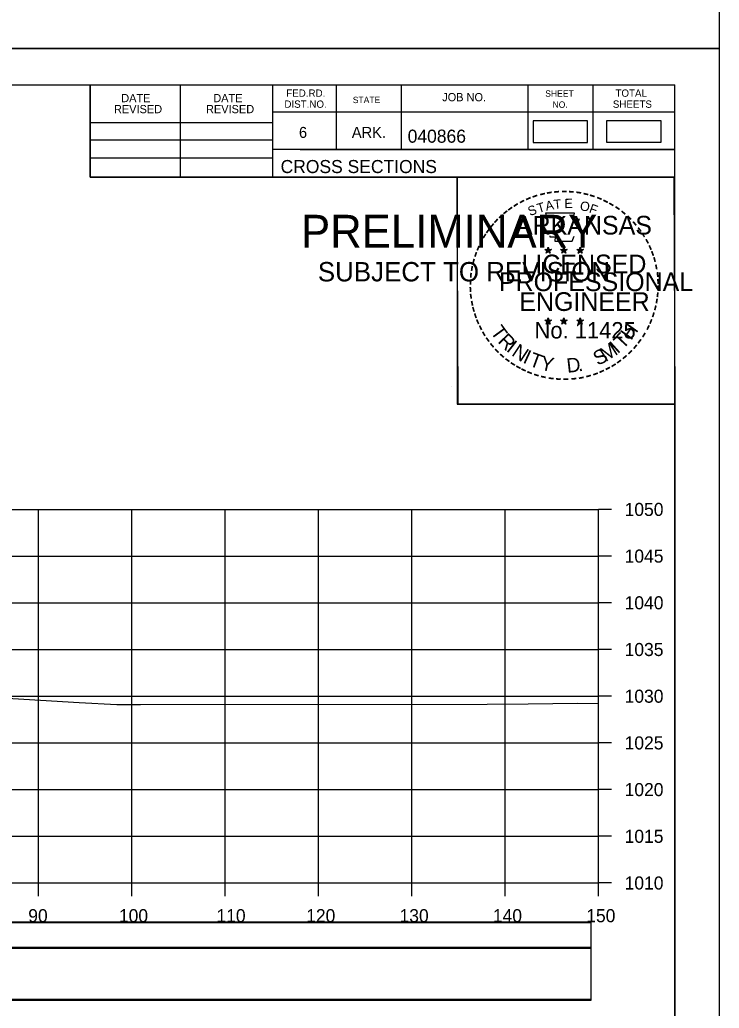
# Model space of a CAD drawing. Extents: x 1370565 to 1374448, y 301010 to 304637.
# Drawn here: x 1373456.8 to 1373531.7, y 302262.2 to 302368.1 of the extents above; entities that cross this region are included whole.
import ezdxf

# ---------------------------------------------------------------- set-up
doc = ezdxf.new("R2010")
doc.units = 0
for name, color, linetype in [('Default', 7, 'Continuous'), ('R_Axis', 7, 'Continuous'), ('R_Axis Annot', 7, 'Continuous'), ('R_Border', 7, 'Continuous'), ('R_Border PE', 7, 'Continuous'), ('R_Border Prem', 7, 'Continuous'), ('R_Drive', 7, 'Continuous'), ('R_Exist Surface', 7, 'Continuous'), ('R_Grid', 7, 'Continuous'), ('R_No Plot', 7, 'Continuous')]:
    doc.layers.add(name, color=color, linetype=linetype)

msp = doc.modelspace()

# ---------------------------------------------------------------- linework, layer by layer
at = {"layer": 'Default'}
for points in [[(1373511.81, 302354.95), (1373517.64, 302354.95), (1373517.64, 302357.26), (1373511.81, 302357.26)], [(1373219.61, 302268.69), (1373518.02, 302268.69), (1373518.02, 302271.39), (1373219.61, 302271.39)], [(1373219.61, 302263.11), (1373518.02, 302263.11), (1373518.02, 302268.63), (1373219.61, 302268.63)]]:
    msp.add_lwpolyline(points, close=True, dxfattribs=at)
at = {"layer": 'R_Axis'}
for p, q in [((1373518.81, 302275.65), (1373518.81, 302315.65)), ((1373520.21, 302315.65), (1373518.81, 302315.65)), ((1373520.21, 302310.65), (1373518.81, 302310.65)), ((1373520.21, 302305.65), (1373518.81, 302305.65)), ((1373520.21, 302300.65), (1373518.81, 302300.65)), ((1373520.21, 302295.65), (1373518.81, 302295.65)), ((1373520.21, 302290.65), (1373518.81, 302290.65)), ((1373520.21, 302285.65), (1373518.81, 302285.65)), ((1373520.21, 302280.65), (1373518.81, 302280.65)), ((1373218.81, 302275.65), (1373518.81, 302275.65)), ((1373458.81, 302274.25), (1373458.81, 302275.65)), ((1373468.81, 302274.25), (1373468.81, 302275.65)), ((1373478.81, 302274.25), (1373478.81, 302275.65)), ((1373488.81, 302274.25), (1373488.81, 302275.65)), ((1373498.81, 302274.25), (1373498.81, 302275.65)), ((1373508.81, 302274.25), (1373508.81, 302275.65)), ((1373518.81, 302274.25), (1373518.81, 302275.65)), ((1373520.21, 302275.65), (1373518.81, 302275.65))]:
    msp.add_line(p, q, dxfattribs=at)
at = {"layer": 'R_Border'}
for p, q in [((1373210.81, 302361.11), (1373526.99, 302361.11)), ((1373464.35, 302351.23), (1373464.35, 302361.11)), ((1373474.03, 302351.23), (1373474.03, 302361.11)), ((1373483.89, 302361.11), (1373483.89, 302351.23)), ((1373490.73, 302361.11), (1373490.73, 302354.17)), ((1373497.67, 302361.11), (1373497.67, 302354.17)), ((1373511.25, 302361.11), (1373511.25, 302354.17)), ((1373518.19, 302361.11), (1373518.19, 302354.17)), ((1373526.99, 302155.65), (1373526.99, 302361.11)), ((1373526.99, 302358.17), (1373483.89, 302358.17)), ((1373526.99, 302358.19), (1373526.99, 302358.19)), ((1373464.35, 302357.09), (1373483.89, 302357.09)), ((1373464.35, 302355.23), (1373483.89, 302355.23)), ((1373526.99, 302354.17), (1373483.89, 302354.17)), ((1373486.85, 302354.17), (1373526.99, 302354.17)), ((1373464.35, 302353.29), (1373483.89, 302353.29)), ((1373526.99, 302351.23), (1373464.35, 302351.23))]:
    msp.add_line(p, q, dxfattribs=at)
at = {"layer": 'R_Border PE'}
for p, q in [((1373513.08, 302343.49), (1373513.43, 302343.37)), ((1373513.08, 302343.49), (1373513.33, 302343.44)), ((1373513.08, 302343.49), (1373513.32, 302343.36)), ((1373513.21, 302343.08), (1373513.43, 302343.37)), ((1373513.21, 302343.08), (1373513.34, 302343.32)), ((1373513.21, 302343.08), (1373513.43, 302343.29)), ((1373513.43, 302343.74), (1373513.39, 302343.49)), ((1373513.43, 302343.37), (1373513.43, 302343.74)), ((1373513.43, 302343.74), (1373513.48, 302343.49)), ((1373513.78, 302343.49), (1373513.43, 302343.37)), ((1373513.64, 302343.08), (1373513.43, 302343.37)), ((1373513.64, 302343.08), (1373513.43, 302343.29)), ((1373513.78, 302343.49), (1373513.49, 302343.44)), ((1373513.64, 302343.08), (1373513.5, 302343.37)), ((1373513.78, 302343.49), (1373513.57, 302343.38)), ((1373514.75, 302343.49), (1373515.1, 302343.37)), ((1373514.75, 302343.49), (1373515, 302343.44)), ((1373514.75, 302343.49), (1373514.99, 302343.36)), ((1373514.88, 302343.08), (1373515.1, 302343.37)), ((1373514.88, 302343.08), (1373515.01, 302343.32)), ((1373514.88, 302343.08), (1373515.1, 302343.29)), ((1373515.1, 302343.74), (1373515.06, 302343.49)), ((1373515.1, 302343.37), (1373515.1, 302343.74)), ((1373515.1, 302343.74), (1373515.15, 302343.49)), ((1373515.45, 302343.49), (1373515.1, 302343.37)), ((1373515.31, 302343.08), (1373515.1, 302343.37)), ((1373515.31, 302343.08), (1373515.1, 302343.29)), ((1373515.45, 302343.49), (1373515.16, 302343.44)), ((1373515.31, 302343.08), (1373515.17, 302343.37)), ((1373515.45, 302343.49), (1373515.24, 302343.38)), ((1373516.51, 302343.47), (1373516.86, 302343.36)), ((1373516.51, 302343.47), (1373516.77, 302343.43)), ((1373516.51, 302343.47), (1373516.75, 302343.35)), ((1373516.65, 302343.07), (1373516.86, 302343.36)), ((1373516.65, 302343.07), (1373516.77, 302343.31)), ((1373516.65, 302343.07), (1373516.86, 302343.28)), ((1373516.86, 302343.73), (1373516.82, 302343.48)), ((1373516.86, 302343.36), (1373516.86, 302343.73)), ((1373516.86, 302343.73), (1373516.91, 302343.48)), ((1373517.21, 302343.47), (1373516.86, 302343.36)), ((1373517.08, 302343.07), (1373516.86, 302343.36)), ((1373517.08, 302343.07), (1373516.86, 302343.28)), ((1373517.21, 302343.47), (1373516.92, 302343.42)), ((1373517.08, 302343.07), (1373516.94, 302343.36)), ((1373517.21, 302343.47), (1373517.01, 302343.37)), ((1373513.08, 302335.91), (1373513.42, 302335.8)), ((1373513.08, 302335.91), (1373513.33, 302335.87)), ((1373513.08, 302335.91), (1373513.31, 302335.79)), ((1373513.21, 302335.5), (1373513.42, 302335.8)), ((1373513.21, 302335.5), (1373513.33, 302335.75)), ((1373513.21, 302335.5), (1373513.42, 302335.72)), ((1373513.42, 302336.17), (1373513.38, 302335.91)), ((1373513.42, 302335.8), (1373513.42, 302336.17)), ((1373513.42, 302336.17), (1373513.47, 302335.92)), ((1373513.77, 302335.91), (1373513.42, 302335.8)), ((1373513.64, 302335.5), (1373513.42, 302335.8)), ((1373513.64, 302335.5), (1373513.42, 302335.72)), ((1373513.77, 302335.91), (1373513.49, 302335.86)), ((1373513.64, 302335.5), (1373513.5, 302335.8)), ((1373513.77, 302335.91), (1373513.57, 302335.81)), ((1373514.74, 302335.91), (1373515.09, 302335.8)), ((1373514.74, 302335.91), (1373515, 302335.87)), ((1373514.74, 302335.91), (1373514.98, 302335.79)), ((1373514.88, 302335.5), (1373515.09, 302335.8)), ((1373514.88, 302335.5), (1373515, 302335.75)), ((1373514.88, 302335.5), (1373515.09, 302335.72)), ((1373515.09, 302336.17), (1373515.05, 302335.91)), ((1373515.09, 302335.8), (1373515.09, 302336.17)), ((1373515.09, 302336.17), (1373515.14, 302335.92)), ((1373515.44, 302335.91), (1373515.09, 302335.8)), ((1373515.31, 302335.5), (1373515.09, 302335.8)), ((1373515.31, 302335.5), (1373515.09, 302335.72)), ((1373515.44, 302335.91), (1373515.15, 302335.86)), ((1373515.31, 302335.5), (1373515.17, 302335.8)), ((1373515.44, 302335.91), (1373515.24, 302335.81)), ((1373516.51, 302335.9), (1373516.86, 302335.79)), ((1373516.51, 302335.9), (1373516.76, 302335.86)), ((1373516.51, 302335.9), (1373516.75, 302335.78)), ((1373516.64, 302335.49), (1373516.86, 302335.79)), ((1373516.64, 302335.49), (1373516.77, 302335.74)), ((1373516.64, 302335.49), (1373516.86, 302335.71)), ((1373516.86, 302336.16), (1373516.82, 302335.9)), ((1373516.86, 302335.79), (1373516.86, 302336.16)), ((1373516.86, 302336.16), (1373516.91, 302335.91)), ((1373517.21, 302335.9), (1373516.86, 302335.79)), ((1373517.07, 302335.49), (1373516.86, 302335.79)), ((1373517.21, 302335.9), (1373516.92, 302335.85)), ((1373517.07, 302335.49), (1373516.94, 302335.79)), ((1373517.21, 302335.9), (1373517, 302335.8)), ((1373517.07, 302335.49), (1373516.86, 302335.71))]:
    msp.add_line(p, q, dxfattribs=at)
for points in [[(1373513.12, 302347.36), (1373513.39, 302346.54)], [(1373516.63, 302346.44), (1373516.77, 302346.73), (1373516.09, 302346.7), (1373516.24, 302347.36), (1373513.12, 302347.36)], [(1373513.61, 302344.94), (1373513.61, 302344.85), (1373514.18, 302344.83), (1373514.12, 302344.36), (1373515.99, 302344.36), (1373516.19, 302344.9)], [(1373513.43, 302343.74), (1373513.64, 302343.08), (1373513.08, 302343.49), (1373513.78, 302343.49), (1373513.21, 302343.08), (1373513.43, 302343.74)], [(1373515.1, 302343.74), (1373515.31, 302343.08), (1373514.75, 302343.49), (1373515.45, 302343.49), (1373514.88, 302343.08), (1373515.1, 302343.74)], [(1373516.86, 302343.73), (1373517.08, 302343.07), (1373516.51, 302343.47), (1373517.21, 302343.47), (1373516.65, 302343.07), (1373516.86, 302343.73)], [(1373513.42, 302336.17), (1373513.64, 302335.5), (1373513.08, 302335.91), (1373513.77, 302335.91), (1373513.21, 302335.5), (1373513.42, 302336.17)], [(1373515.09, 302336.17), (1373515.31, 302335.5), (1373514.74, 302335.91), (1373515.44, 302335.91), (1373514.88, 302335.5), (1373515.09, 302336.17)], [(1373516.86, 302336.16), (1373517.07, 302335.49), (1373516.51, 302335.9), (1373517.21, 302335.9), (1373516.64, 302335.49), (1373516.86, 302336.16)]]:
    msp.add_lwpolyline(points, dxfattribs=at)
for centre, radius in [((1373513.43, 302343.37), 0.172), ((1373513.43, 302343.37), 0.145), ((1373513.43, 302343.37), 0.116), ((1373513.43, 302343.37), 0.0991), ((1373513.43, 302343.37), 0.0747), ((1373513.43, 302343.37), 0.0495), ((1373513.43, 302343.37), 0.0296), ((1373515.1, 302343.37), 0.172), ((1373515.1, 302343.37), 0.145), ((1373515.1, 302343.37), 0.116), ((1373515.1, 302343.37), 0.0991), ((1373515.1, 302343.37), 0.0747), ((1373515.1, 302343.37), 0.0495), ((1373515.1, 302343.37), 0.0296), ((1373516.86, 302343.36), 0.172), ((1373516.86, 302343.36), 0.145), ((1373516.86, 302343.36), 0.116), ((1373516.86, 302343.36), 0.0991), ((1373516.86, 302343.36), 0.0747), ((1373516.86, 302343.36), 0.0495), ((1373516.86, 302343.36), 0.0296), ((1373513.42, 302335.8), 0.172), ((1373513.42, 302335.8), 0.145), ((1373513.42, 302335.8), 0.116), ((1373513.42, 302335.8), 0.0991), ((1373513.42, 302335.8), 0.0747), ((1373513.42, 302335.8), 0.0495), ((1373513.42, 302335.8), 0.0296), ((1373515.09, 302335.8), 0.172), ((1373515.09, 302335.8), 0.145), ((1373515.09, 302335.8), 0.116), ((1373515.09, 302335.8), 0.0991), ((1373515.09, 302335.8), 0.0747), ((1373515.09, 302335.8), 0.0495), ((1373515.09, 302335.8), 0.0296), ((1373516.86, 302335.79), 0.172), ((1373516.86, 302335.79), 0.145), ((1373516.86, 302335.79), 0.116), ((1373516.86, 302335.79), 0.0991), ((1373516.86, 302335.79), 0.0747), ((1373516.86, 302335.79), 0.0495), ((1373516.86, 302335.79), 0.0296)]:
    msp.add_circle(centre, radius, dxfattribs=at)
at = {"layer": 'R_Drive'}
for points in [[(1373519.68, 302354.96), (1373525.51, 302354.96), (1373525.51, 302357.27), (1373519.68, 302357.27)], [(1373219.61, 302268.74), (1373518.02, 302268.74), (1373518.02, 302271.45), (1373219.61, 302271.45)], [(1373219.61, 302263.22), (1373518.02, 302263.22), (1373518.02, 302268.74), (1373219.61, 302268.74)]]:
    msp.add_lwpolyline(points, close=True, dxfattribs=at)
at = {"layer": 'R_Exist Surface'}
msp.add_lwpolyline([(1373268.65, 302291.32), (1373313.93, 302292.02), (1373320.33, 302292.12), (1373327.73, 302292.13), (1373371.56, 302292.45), (1373381.12, 302293.26), (1373382.52, 302293.32), (1373384.77, 302294.16), (1373402.08, 302300.84), (1373410.16, 302301), (1373411.85, 302301.04), (1373413.89, 302301.01), (1373422.5, 302300.9), (1373441.9, 302297.01), (1373447.77, 302295.9), (1373463.18, 302294.99), (1373467.23, 302294.76), (1373469.74, 302294.76), (1373506.89, 302294.78), (1373511.29, 302294.84), (1373516.55, 302294.89), (1373518.81, 302294.87)], dxfattribs=at)
at = {"layer": 'R_Grid'}
for p, q in [((1373218.81, 302315.65), (1373518.81, 302315.65)), ((1373458.81, 302275.65), (1373458.81, 302315.65)), ((1373468.81, 302275.65), (1373468.81, 302315.65)), ((1373478.81, 302275.65), (1373478.81, 302315.65)), ((1373488.81, 302275.65), (1373488.81, 302315.65)), ((1373498.81, 302275.65), (1373498.81, 302315.65)), ((1373508.81, 302275.65), (1373508.81, 302315.65)), ((1373518.81, 302275.65), (1373518.81, 302315.65)), ((1373218.81, 302310.65), (1373518.81, 302310.65)), ((1373218.81, 302305.65), (1373518.81, 302305.65)), ((1373218.81, 302300.65), (1373518.81, 302300.65)), ((1373218.81, 302295.65), (1373518.81, 302295.65)), ((1373218.81, 302290.65), (1373518.81, 302290.65)), ((1373218.81, 302285.65), (1373518.81, 302285.65)), ((1373218.81, 302280.65), (1373518.81, 302280.65)), ((1373218.81, 302275.65), (1373518.81, 302275.65))]:
    msp.add_line(p, q, dxfattribs=at)
at = {"layer": 'R_No Plot'}
for p, q in [((1373198.41, 302365.01), (1373531.75, 302365.01)), ((1373198.41, 302365), (1373531.75, 302365)), ((1373503.03, 302328.77), (1373503.03, 302328.77))]:
    msp.add_line(p, q, dxfattribs=at)
for points in [[(1373198.41, 302578.34), (1373531.75, 302578.34), (1373531.75, 302365.01), (1373198.41, 302365.01)], [(1373198.41, 302365), (1373531.75, 302365), (1373531.75, 302151.67), (1373198.41, 302151.67)], [(1373444.73, 302361.11), (1373464.35, 302361.11), (1373464.35, 302351.23), (1373480.47, 302351.23), (1373503.67, 302351.23), (1373503.67, 302326.9), (1373526.99, 302326.9), (1373526.99, 302155.65), (1373210.81, 302155.65), (1373210.81, 302361.11)], [(1373503.67, 302351.23), (1373526.87, 302351.23), (1373526.99, 302326.9), (1373503.79, 302326.9)]]:
    msp.add_lwpolyline(points, close=True, dxfattribs=at)

# ---------------------------------------------------------------- texts
at = {"layer": 'R_Axis Annot'}
for s, p in [('1050', (1373521.61, 302314.95)), ('1045', (1373521.61, 302309.95)), ('1040', (1373521.61, 302304.95)), ('1035', (1373521.61, 302299.95)), ('1030', (1373521.61, 302294.95)), ('1025', (1373521.61, 302289.95)), ('1020', (1373521.61, 302284.95)), ('1015', (1373521.61, 302279.95)), ('1010', (1373521.61, 302274.95)), ('90', (1373457.73, 302271.45)), ('100', (1373467.44, 302271.45)), ('110', (1373477.89, 302271.45)), ('120', (1373487.5, 302271.45)), ('130', (1373497.5, 302271.45)), ('140', (1373507.5, 302271.45)), ('150', (1373517.5, 302271.45))]:
    msp.add_text(s, height=1.4, dxfattribs=at).set_placement(p)
at = {"layer": 'R_Border'}
for s, height, p in [('DATE', 0.879, (1373467.69, 302359.25)), ('DATE', 0.879, (1373477.55, 302359.25)), ('FED.RD.', 0.782, (1373485.37, 302359.83)), ('JOB NO.', 0.879, (1373502.07, 302359.35)), ('SHEET', 0.684, (1373513.11, 302359.83)), ('TOTAL', 0.782, (1373520.63, 302359.83)), ('DIST.NO.', 0.782, (1373485.17, 302358.65)), ('STATE', 0.684, (1373492.49, 302359.15)), ('NO.', 0.684, (1373513.89, 302358.65)), ('SHEETS', 0.782, (1373520.35, 302358.65)), ('REVISED', 0.879, (1373466.91, 302358.07)), ('REVISED', 0.879, (1373476.77, 302358.07)), ('6', 1.17, (1373486.73, 302355.43)), ('ARK.', 1.172, (1373492.39, 302355.43)), ('040866', 1.4, (1373498.37, 302354.91)), ('CROSS SECTIONS', 1.4, (1373484.76, 302351.66))]:
    msp.add_text(s, height=height, rotation=360, dxfattribs=at).set_placement(p)
at = {"layer": 'R_Border PE'}
for s, height, rotation, p in [('-', 1.6, 13.6301, (1373512.62, 302348.73)), ('-', 1.6, 10.2193, (1373513.3, 302348.89)), ('-', 1.6, 5.8968, (1373514.03, 302349)), ('-', 1.6, 0.1862, (1373514.8, 302349.08)), ('-', 1.6, 357.743, (1373515.52, 302349.06)), ('-', 1.6, 352.1617, (1373516.26, 302349.01)), ('-', 1.6, 347.2049, (1373516.98, 302348.89)), ('-', 1.6, 34.0636, (1373510, 302347.53)), ('-', 1.6, 28.7918, (1373510.6, 302347.9)), ('-', 1.6, 24.3072, (1373511.23, 302348.22)), ('-', 1.6, 19.1761, (1373511.87, 302348.49)), ('T', 1, 16.4036, (1373512.39, 302347.37)), ('A', 1, 11.2132, (1373513.22, 302347.62)), ('T', 1, 6.0228, (1373514.06, 302347.79)), ('E', 1, 0.8323, (1373515.17, 302347.9)), ('O', 1, 350.4515, (1373516.77, 302347.69)), ('-', 1.6, 342.3362, (1373517.62, 302348.74)), ('-', 1.6, 337.8551, (1373518.35, 302348.51)), ('-', 1.6, 334.1211, (1373518.98, 302348.24)), ('-', 1.6, 329.6409, (1373519.56, 302347.96)), ('-', 1.6, 38.9507, (1373508.95, 302346.76)), ('-', 1.6, 36.2317, (1373509.43, 302347.14)), ('S', 1, 21.594, (1373511.48, 302347.04)), ('F', 1, 340.0707, (1373517.73, 302347.46)), ('-', 1.6, 325.8627, (1373520.21, 302347.6)), ('-', 1.6, 320.5297, (1373520.82, 302347.17)), ('-', 1.6, 50.6142, (1373507.67, 302345.38)), ('-', 1.6, 48.423, (1373508.07, 302345.87)), ('-', 1.6, 42.9622, (1373508.52, 302346.34)), ('ARKANSAS', 2, 360, (1373509.97, 302345.08)), ('-', 1.6, 315.5786, (1373521.42, 302346.69)), ('-', 1.6, 309.8797, (1373521.98, 302346.14)), ('-', 1.6, 54.2325, (1373507.25, 302344.81)), ('-', 1.6, 306.6522, (1373522.51, 302345.53)), ('-', 1.4, 303.6753, (1373523, 302344.97)), ('-', 1.6, 62.8713, (1373506.62, 302343.67)), ('-', 1.6, 58.0706, (1373506.93, 302344.29)), ('-', 1.6, 299.6684, (1373523.31, 302344.36)), ('-', 1.6, 72.3945, (1373506.14, 302342.43)), ('-', 1.6, 67.7743, (1373506.36, 302343.06)), ('DWB', 0.01, 360, (1373513.42, 302343.37)), ('DWB', 0.01, 360, (1373515.09, 302343.37)), ('DWB', 0.01, 360, (1373516.85, 302343.36)), ('-', 1.6, 294.6628, (1373523.64, 302343.75)), ('-', 1.6, 290.5728, (1373523.9, 302343.17)), ('-', 1.6, 75.461, (1373505.94, 302341.72)), ('LICENSED', 2, 360, (1373510.57, 302340.93)), ('-', 1.6, 285.1233, (1373524.13, 302342.59)), ('-', 1.6, 81.2013, (1373505.81, 302341)), ('PROFESSIONAL', 2, 360, (1373508.15, 302339.02)), ('-', 1.6, 280.5493, (1373524.33, 302341.85)), ('-', 1.6, 276.5962, (1373524.49, 302341.08)), ('-', 1.6, 89.0622, (1373505.71, 302339.61)), ('-', 1.6, 85.1863, (1373505.73, 302340.31)), ('-', 1.6, 274.3301, (1373524.55, 302340.36)), ('-', 1.6, 94.1959, (1373505.74, 302338.89)), ('ENGINEER', 2, 360, (1373510.33, 302336.9)), ('-', 1.6, 263.5172, (1373524.57, 302339.06)), ('-', 1.6, 269.9407, (1373524.59, 302339.73)), ('-', 1.6, 98.9479, (1373505.81, 302338.22)), ('-', 1.6, 101.7149, (1373505.95, 302337.49)), ('-', 1.6, 260.9953, (1373524.5, 302338.41)), ('-', 1.6, 105.4578, (1373506.11, 302336.89)), ('-', 1.6, 255.7626, (1373524.39, 302337.73)), ('-', 1.6, 109.0874, (1373506.33, 302336.26)), ('-', 1.6, 114.0643, (1373506.58, 302335.67)), ('No. 11425', 1.757, 360, (1373511.96, 302333.95)), ('DWB', 0.01, 360, (1373513.41, 302335.8)), ('DWB', 0.01, 360, (1373515.08, 302335.8)), ('DWB', 0.01, 360, (1373516.85, 302335.79)), ('-', 1.6, 247.8887, (1373523.98, 302336.33)), ('-', 1.6, 252.8681, (1373524.2, 302337.01)), ('-', 1.6, 115.7289, (1373506.89, 302335.05)), ('-', 1.6, 120.4471, (1373507.24, 302334.46)), ('T', 1.54, 306.0406, (1373507.18, 302334.64)), ('T', 1.54, 46.6444, (1373521.41, 302332.73)), ('H', 1.54, 54.6088, (1373522.3, 302333.67)), ('-', 1.6, 244.6197, (1373523.72, 302335.71)), ('-', 1.6, 125.8934, (1373507.65, 302333.9)), ('R', 1.54, 314.005, (1373507.95, 302333.59)), ('I', 1.54, 321.9694, (1373508.85, 302332.66)), ('I', 1.54, 42.1136, (1373520.85, 302332.25)), ('-', 1.6, 233.8452, (1373522.92, 302334.3)), ('-', 1.6, 239.0712, (1373523.33, 302334.95)), ('-', 1.6, 130.7181, (1373508.11, 302333.35)), ('-', 1.6, 134.2238, (1373508.62, 302332.8)), ('N', 1.54, 326.5002, (1373509.41, 302332.19)), ('I', 1.54, 335.3603, (1373510.62, 302331.4)), ('S', 1.54, 26.9312, (1373518.73, 302331)), ('M', 1.54, 32.6563, (1373519.57, 302331.41)), ('-', 1.6, 225.7653, (1373522.01, 302333.17)), ('-', 1.6, 231.2538, (1373522.49, 302333.73)), ('-', 1.6, 138.9338, (1373509.15, 302332.34)), ('-', 1.6, 144.6463, (1373509.71, 302331.93)), ('T', 1.54, 339.8912, (1373511.28, 302331.07)), ('Y', 1.54, 347.8556, (1373512.5, 302330.63)), ('D', 1.54, 6.3969, (1373515.48, 302330.27)), ('-', 1.6, 215.7363, (1373520.94, 302332.19)), ('-', 1.6, 221.0851, (1373521.49, 302332.66)), ('-', 1.6, 148.0898, (1373510.27, 302331.56)), ('-', 1.6, 151.5704, (1373510.85, 302331.24)), ('-', 1.6, 154.6002, (1373511.37, 302330.99)), ('-', 1.6, 158.5612, (1373511.99, 302330.74)), ('.', 1.54, 13.7642, (1373516.68, 302330.4)), ('-', 1.6, 204.2516, (1373519.23, 302331.14)), ('-', 1.6, 207.3568, (1373519.85, 302331.46)), ('-', 1.6, 212.2491, (1373520.41, 302331.8)), ('-', 1.6, 162.7983, (1373512.68, 302330.52)), ('-', 1.6, 167.5555, (1373513.39, 302330.36)), ('-', 1.6, 173.1155, (1373514.17, 302330.25)), ('-', 1.6, 176.5183, (1373514.91, 302330.2)), ('-', 1.6, 181.5918, (1373515.66, 302330.22)), ('-', 1.6, 185.8167, (1373516.47, 302330.29)), ('-', 1.6, 191.2858, (1373517.2, 302330.42)), ('-', 1.6, 195.4743, (1373517.93, 302330.62)), ('-', 1.6, 200.7184, (1373518.61, 302330.86))]:
    msp.add_text(s, height=height, rotation=rotation, dxfattribs=at).set_placement(p)
at = {"layer": 'R_Border Prem'}
for s, height, p in [('PRELIMINARY', 3.5, (1373486.95, 302343.69)), ('DWB', 0.01, (1373487.69, 302345.54)), ('SUBJECT TO REVISION', 2.0751, (1373488.75, 302340.06))]:
    msp.add_text(s, height=height, rotation=360, dxfattribs=at).set_placement(p)

doc.saveas('drawing.dxf')
